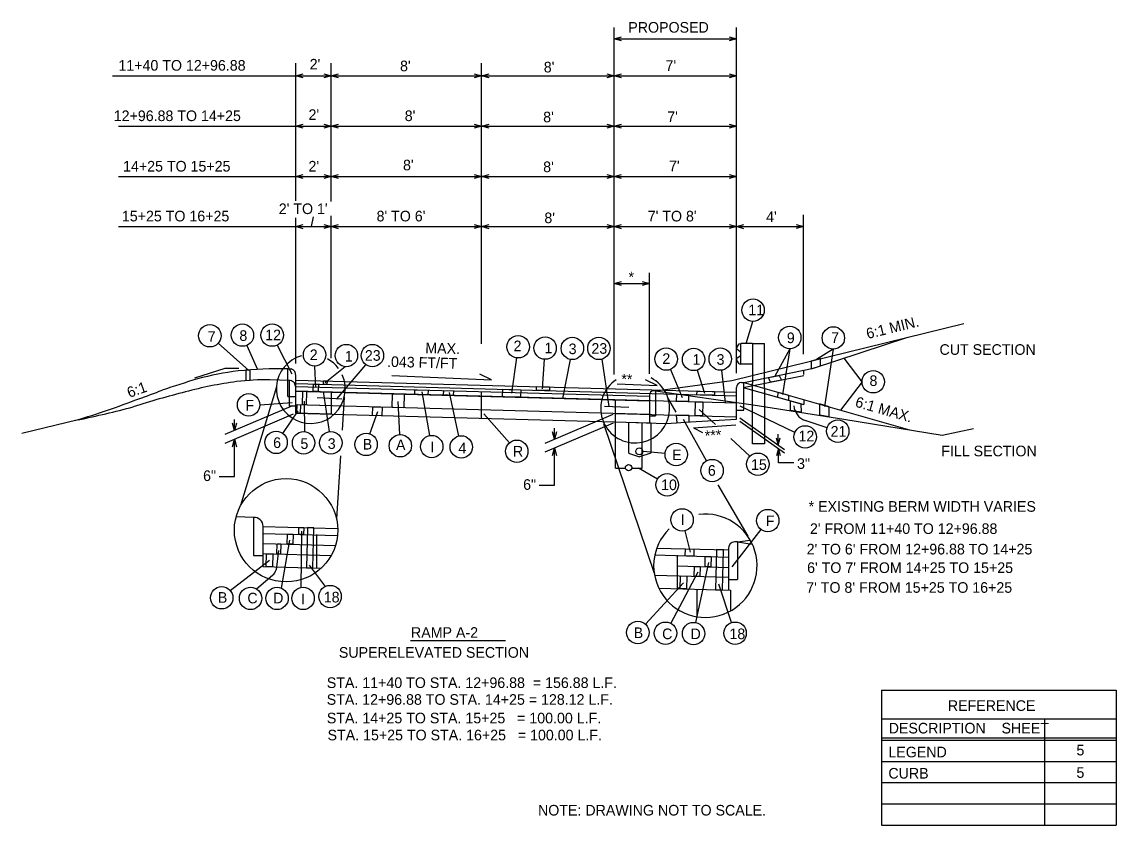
# Model space of a CAD drawing. Extents: x -210 to 558, y -150 to 205.
# Drawn here: x 374.7 to 436.5, y -53.8 to -8.4 of the extents above; entities that cross this region are included whole.
import ezdxf

# ---------------------------------------------------------------- set-up
doc = ezdxf.new("R2010")
doc.units = 0
for name, color, linetype in [('Level 4', 7, 'Continuous'), ('Level 6', 7, 'Continuous'), ('Level 60', 7, 'Continuous'), ('Level 7', 7, 'Continuous')]:
    doc.layers.add(name, color=color, linetype=linetype)

msp = doc.modelspace()

# ---------------------------------------------------------------- linework, layer by layer
at = {"layer": 'Level 4'}
for p, q in [((408.184, -28.302), (408.184, -8.684)), ((415.094, -28.229), (415.094, -8.684)), ((408.184, -9.336), (415.094, -9.336)), ((390.196, -18.485), (390.196, -10.711)), ((392.196, -18.522), (392.196, -10.711)), ((400.696, -26.569), (400.696, -10.711)), ((379.849, -11.429), (390.196, -11.429)), ((390.196, -11.429), (392.196, -11.429)), ((392.196, -11.429), (400.696, -11.429)), ((400.549, -11.411), (400.966, -11.411)), ((400.696, -11.429), (408.184, -11.429)), ((408.184, -11.429), (415.094, -11.429)), ((380.181, -14.268), (390.196, -14.268)), ((390.196, -14.268), (392.196, -14.268)), ((392.196, -14.268), (400.696, -14.268)), ((400.549, -14.25), (400.966, -14.25)), ((400.696, -14.268), (408.184, -14.268)), ((408.184, -14.268), (415.094, -14.268)), ((380.181, -17.107), (390.196, -17.107)), ((390.196, -17.107), (392.196, -17.107)), ((392.196, -17.107), (400.696, -17.107)), ((400.549, -17.089), (400.966, -17.089)), ((400.696, -17.107), (408.184, -17.107)), ((408.184, -17.107), (415.094, -17.107)), ((390.196, -27.673), (390.196, -19.448)), ((391.184, -19.392), (391.071, -19.94)), ((392.196, -27.378), (392.196, -19.335)), ((418.884, -27.152), (418.884, -19.284)), ((380.181, -19.946), (390.196, -19.946)), ((390.196, -19.946), (392.196, -19.946)), ((392.196, -19.946), (400.696, -19.946)), ((400.549, -19.928), (400.966, -19.928)), ((400.696, -19.946), (408.184, -19.946)), ((408.184, -19.946), (418.884, -19.946)), ((410.184, -28.255), (410.184, -22.558)), ((408.184, -23.158), (410.184, -23.158)), ((415.652, -26.553), (416.028, -25.298)), ((385.816, -26.532), (387.54, -28.071)), ((387.439, -26.655), (388.041, -28.017)), ((389.157, -26.64), (389.983, -28.255)), ((418.105, -26.847), (417.238, -28.44)), ((418.105, -26.847), (417.7, -29.422)), ((420.566, -26.871), (419.619, -27.457)), ((420.566, -26.871), (420.061, -30.103)), ((392.538, -29.66), (394.166, -27.754)), ((402.671, -27.362), (402.384, -29.353)), ((404.239, -27.439), (404.121, -29.12)), ((405.701, -27.446), (405.267, -29.657)), ((407.495, -27.434), (407.88, -30.103)), ((422.189, -28.711), (421.179, -27.379)), ((386.196, -27.962), (384.483, -28.51)), ((386.979, -27.965), (386.196, -27.962)), ((391.258, -27.849), (391.318, -29.014)), ((392.99, -27.863), (391.862, -28.772)), ((395.631, -28.356), (401.257, -28.609)), ((401.257, -28.609), (400.592, -28.289)), ((411.369, -28.011), (412.034, -29.609)), ((412.869, -28.053), (413.284, -29.354)), ((414.254, -28.056), (414.465, -29.875)), ((408.363, -28.838), (410.621, -28.922)), ((410.621, -28.922), (409.956, -28.602)), ((422.189, -28.711), (420.973, -30.313)), ((392.112, -31.525), (391.759, -29.264)), ((397.771, -31.753), (397.347, -29.285)), ((399.417, -31.778), (398.887, -29.321)), ((390.019, -30.068), (386.183, -31.7)), ((388.171, -30.016), (389.992, -29.878)), ((390.703, -31.529), (390.697, -29.808)), ((396.075, -31.69), (395.986, -29.822)), ((412.989, -30.274), (413.904, -31.119)), ((418.387, -31.584), (415.31, -30.095)), ((390.051, -30.552), (386.183, -32.197)), ((386.738, -31.464), (386.738, -30.835)), ((389.467, -31.626), (390.335, -30.351)), ((394.386, -31.655), (394.84, -30.395)), ((402.265, -32.166), (400.821, -30.525)), ((408.102, -30.565), (404.266, -32.197)), ((413.409, -33.176), (412.11, -30.837)), ((415.285, -30.758), (417.806, -32.545)), ((420.216, -31.306), (418.975, -30.906)), ((408.133, -31.049), (404.266, -32.694)), ((404.82, -31.961), (404.82, -31.332)), ((412.671, -31.315), (415.064, -31.144)), ((412.671, -31.315), (413.185, -31.579)), ((415.285, -30.941), (417.815, -32.733)), ((386.738, -34.061), (386.738, -31.961)), ((414.77, -31.919), (415.845, -32.912)), ((417.451, -32.295), (417.451, -31.666)), ((404.82, -34.558), (404.82, -32.459)), ((411.072, -32.763), (409.817, -32.643)), ((417.461, -33.295), (417.461, -32.48)), ((418.337, -33.295), (417.461, -33.295)), ((410.634, -34.216), (409.553, -33.59)), ((385.862, -34.061), (386.738, -34.061)), ((403.944, -34.558), (404.82, -34.558)), ((416.474, -37.06), (414.84, -39.173)), ((389.395, -40.371), (389.868, -37.672)), ((390.516, -37.148), (390.486, -40.33)), ((412.177, -37.132), (412.481, -38.339)), ((389.228, -38.24), (389.086, -39.332)), ((386.493, -40.501), (388.722, -38.8)), ((412.806, -42.324), (413.539, -38.929)), ((390.96, -39.084), (391.86, -40.281)), ((411.384, -42.363), (412.929, -39.458)), ((387.987, -40.416), (388.891, -39.643)), ((409.948, -42.415), (412.095, -40.068)), ((414.819, -42.32), (414.108, -40.149)), ((396.676, -43.325), (402.05, -43.325)), ((423.287, -46.13), (423.287, -53.765)), ((423.287, -46.13), (436.542, -46.13)), ((436.542, -46.13), (436.542, -53.765)), ((423.287, -47.765), (436.542, -47.765)), ((432.497, -47.765), (432.497, -53.765)), ((423.287, -48.839), (436.542, -48.839)), ((423.287, -48.965), (436.542, -48.965)), ((423.287, -50.165), (436.542, -50.165)), ((423.287, -51.365), (436.542, -51.365)), ((423.287, -52.565), (436.542, -52.565)), ((423.287, -53.765), (436.542, -53.765))]:
    msp.add_line(p, q, dxfattribs=at)
for points in [[(408.604, -9.452), (408.184, -9.336), (408.604, -9.224)], [(414.674, -9.22), (415.094, -9.336), (414.674, -9.448)], [(390.616, -11.545), (390.196, -11.429), (390.616, -11.317)], [(391.776, -11.313), (392.196, -11.429), (391.776, -11.541)], [(392.616, -11.545), (392.196, -11.429), (392.616, -11.317)], [(400.276, -11.313), (400.696, -11.429), (400.276, -11.541)], [(401.116, -11.545), (400.696, -11.429), (401.116, -11.317)], [(407.764, -11.313), (408.184, -11.429), (407.764, -11.541)], [(408.604, -11.545), (408.184, -11.429), (408.604, -11.317)], [(414.674, -11.313), (415.094, -11.429), (414.674, -11.541)], [(390.616, -14.384), (390.196, -14.268), (390.616, -14.156)], [(391.776, -14.152), (392.196, -14.268), (391.776, -14.38)], [(392.616, -14.384), (392.196, -14.268), (392.616, -14.156)], [(400.276, -14.152), (400.696, -14.268), (400.276, -14.38)], [(401.116, -14.384), (400.696, -14.268), (401.116, -14.156)], [(407.764, -14.152), (408.184, -14.268), (407.764, -14.38)], [(408.604, -14.384), (408.184, -14.268), (408.604, -14.156)], [(414.674, -14.152), (415.094, -14.268), (414.674, -14.38)], [(390.616, -17.223), (390.196, -17.107), (390.616, -16.995)], [(391.776, -16.991), (392.196, -17.107), (391.776, -17.219)], [(392.616, -17.223), (392.196, -17.107), (392.616, -16.995)], [(400.276, -16.991), (400.696, -17.107), (400.276, -17.219)], [(401.116, -17.223), (400.696, -17.107), (401.116, -16.995)], [(407.764, -16.991), (408.184, -17.107), (407.764, -17.219)], [(408.604, -17.223), (408.184, -17.107), (408.604, -16.995)], [(414.674, -16.991), (415.094, -17.107), (414.674, -17.219)], [(390.616, -20.062), (390.196, -19.946), (390.616, -19.834)], [(391.776, -19.83), (392.196, -19.946), (391.776, -20.058)], [(392.616, -20.062), (392.196, -19.946), (392.616, -19.834)], [(400.276, -19.83), (400.696, -19.946), (400.276, -20.058)], [(401.116, -20.062), (400.696, -19.946), (401.116, -19.834)], [(407.764, -19.83), (408.184, -19.946), (407.764, -20.058)], [(408.604, -20.062), (408.184, -19.946), (408.604, -19.834)], [(414.674, -19.83), (415.094, -19.946), (414.674, -20.058)], [(415.514, -20.062), (415.094, -19.946), (415.514, -19.834)], [(418.464, -19.83), (418.884, -19.946), (418.464, -20.058)], [(408.604, -23.274), (408.184, -23.158), (408.604, -23.046)], [(409.764, -23.042), (410.184, -23.158), (409.764, -23.27)], [(386.854, -31.044), (386.738, -31.464), (386.626, -31.044)], [(386.622, -32.381), (386.738, -31.961), (386.85, -32.381)], [(404.936, -31.541), (404.82, -31.961), (404.708, -31.541)], [(417.335, -31.875), (417.451, -32.295), (417.563, -31.875)], [(404.704, -32.879), (404.82, -32.459), (404.932, -32.879)], [(417.577, -32.9), (417.461, -32.48), (417.349, -32.9)]]:
    msp.add_lwpolyline(points, dxfattribs=at)
for points in [[(419.308, -27.539), (419.322, -27.979), (419.849, -27.815), (419.846, -27.389)], [(416.896, -28.471), (417.509, -28.351), (417.638, -28.612), (417.026, -28.732)], [(417.443, -29.306), (418.043, -29.476), (418.041, -29.767), (417.44, -29.597)], [(418.144, -29.793), (418.737, -29.959), (418.747, -30.437), (418.152, -30.344)], [(419.79, -29.96), (419.789, -30.583), (420.328, -30.674), (420.324, -30.123)]]:
    msp.add_lwpolyline(points, close=True, dxfattribs=at)
for centre in [(416.03, -24.664), (385.343, -26.11), (387.183, -26.075), (388.868, -26.075), (418.106, -26.213), (420.567, -26.237), (391.263, -27.189), (402.761, -26.734), (404.283, -26.806), (405.823, -26.824), (407.323, -26.824), (393.057, -27.233), (394.527, -27.233), (411.125, -27.426), (412.676, -27.449), (414.181, -27.426), (422.823, -28.712), (387.537, -30.015), (420.818, -31.506), (389.088, -32.135), (418.975, -31.83), (390.642, -32.161), (392.178, -32.161), (394.172, -32.252), (396.106, -32.324), (397.878, -32.377), (399.551, -32.397), (402.684, -32.642), (411.692, -32.823), (416.302, -33.372), (413.717, -33.73), (411.183, -34.533), (412.022, -36.517), (416.862, -36.558), (386.013, -40.916), (387.647, -40.951), (389.139, -40.951), (390.613, -40.951), (392.138, -40.851), (409.52, -42.882), (411.086, -42.923), (412.672, -42.943), (415.016, -42.923)]:
    msp.add_circle(centre, 0.634, dxfattribs=at)
for centre, radius, start, end in [((419.305, -29.997), 0.967, 184.63452, 250.04639), ((388.603, -39.245), 0.491, 305.90709, 349.76504)]:
    msp.add_arc(centre, radius, start, end, dxfattribs=at)
at = {"layer": 'Level 6'}
for p, q in [((414.826, -28.635), (427.937, -25.416)), ((389.82, -28.64), (388.731, -28.607)), ((389.82, -28.64), (389.82, -30.072)), ((390.175, -28.959), (390.175, -30.487)), ((390.175, -28.974), (410.184, -29.524)), ((410.517, -29.221), (414.826, -28.635)), ((390.175, -29.239), (410.184, -29.789)), ((400.696, -30.776), (400.696, -29.264)), ((410.184, -29.47), (410.184, -31.037)), ((410.517, -29.221), (410.416, -29.221)), ((410.517, -29.221), (410.517, -30.631)), ((410.517, -29.221), (416.037, -30.01)), ((389.82, -30.072), (390.175, -30.072)), ((390.175, -30.001), (410.184, -30.551)), ((416.037, -30.01), (421.152, -30.817)), ((377.912, -30.866), (374.726, -31.638)), ((390.175, -30.487), (410.263, -31.039)), ((410.184, -30.631), (410.517, -30.631)), ((421.152, -30.817), (426.711, -31.73)), ((408.989, -31.004), (408.989, -32.734)), ((410.263, -31.039), (410.263, -32.734)), ((426.711, -31.73), (428.492, -31.361)), ((408.989, -32.739), (409.626, -32.948)), ((410.263, -32.739), (409.626, -32.948)), ((387.811, -36.381), (386.827, -36.352)), ((387.811, -36.381), (387.811, -38.53)), ((388.344, -36.86), (388.344, -39.152)), ((388.344, -36.883), (392.57, -36.999)), ((388.344, -37.28), (392.557, -37.395)), ((391.375, -37.334), (391.375, -39.235)), ((415.148, -37.762), (415.878, -37.663)), ((388.379, -37.846), (392.443, -37.957)), ((410.599, -38.106), (414.648, -38.217)), ((414.648, -38.136), (414.648, -40.486)), ((415.148, -37.762), (414.996, -37.762)), ((415.148, -37.762), (415.148, -39.877)), ((415.148, -37.762), (415.977, -37.881)), ((387.811, -38.53), (388.344, -38.53)), ((388.344, -38.423), (392.199, -38.529)), ((410.456, -38.499), (414.648, -38.614)), ((411.759, -40.407), (411.759, -38.505)), ((388.344, -39.152), (391.638, -39.242)), ((411.759, -39.12), (414.648, -39.2)), ((410.464, -39.642), (414.648, -39.757)), ((414.648, -39.877), (415.148, -39.877)), ((410.713, -40.378), (414.767, -40.489)), ((412.856, -40.437), (412.856, -41.992)), ((414.767, -40.489), (414.767, -41.657))]:
    msp.add_line(p, q, dxfattribs=at)
msp.add_circle((409.61, -32.648), 0.196, dxfattribs=at)
for centre, radius, start, end in [((389.771, -50.813), 22.298, 97.5041, 105.09419), ((388.416, -40.406), 11.803, 88.4676, 97.57992), ((389.842, -28.981), 0.342, 1.12623, 93.69626), ((396.565, -78.792), 51.086, 104.27965, 107.71771), ((410.425, -29.463), 0.242, 92.27579, 181.84757), ((364.744, 31.6), 63.839, 281.90418, 284.7694), ((387.844, -36.893), 0.513, 1.12623, 93.69626), ((415.011, -38.125), 0.363, 92.27579, 181.84757)]:
    msp.add_arc(centre, radius, start, end, dxfattribs=at)
at = {"layer": 'Level 60'}
for points in [[(387.62, -28.051), (387.385, -28.065), (387.385, -28.64), (387.627, -28.626)], [(391.18, -29.247), (391.191, -28.845), (391.479, -28.853), (391.468, -29.255)], [(391.764, -28.861), (391.77, -28.655), (391.967, -28.66), (391.961, -28.866)], [(403.799, -29.191), (403.804, -28.986), (404.535, -29.006), (404.529, -29.212)], [(390.573, -30.012), (390.594, -29.25), (390.806, -29.256), (390.785, -30.018)], [(395.646, -30.16), (395.667, -29.398), (396.328, -29.417), (396.307, -30.178)], [(396.918, -29.433), (396.925, -29.169), (397.671, -29.189), (397.664, -29.453)], [(398.548, -29.458), (398.565, -29.196), (399.102, -29.229), (399.086, -29.491)], [(401.881, -29.56), (401.893, -29.139), (402.904, -29.167), (402.892, -29.588)], [(411.716, -29.811), (411.727, -29.409), (412.387, -29.428), (412.376, -29.829)], [(412.862, -29.441), (412.867, -29.235), (413.858, -29.262), (413.853, -29.468)], [(390.266, -30.489), (390.279, -30.004), (390.461, -30.009), (390.447, -30.494)], [(394.535, -30.615), (394.549, -30.13), (395.075, -30.144), (395.062, -30.63)], [(412.768, -30.622), (412.79, -29.841), (413.198, -29.852), (413.177, -30.633)], [(411.717, -31.023), (412.422, -30.973), (412.422, -30.613), (411.692, -30.592)], [(390.369, -37.335), (390.38, -36.939), (390.654, -36.947), (390.643, -37.343)], [(390.867, -36.952), (390.805, -39.219), (391.16, -39.229), (391.222, -36.962)], [(389.713, -37.882), (389.728, -37.318), (390.051, -37.326), (390.035, -37.891)], [(389.126, -38.444), (389.142, -37.867), (389.348, -37.872), (389.332, -38.45)], [(412.205, -38.547), (412.216, -38.151), (412.695, -38.164), (412.684, -38.56)], [(413.973, -38.199), (413.911, -40.466), (414.304, -40.477), (414.367, -38.21)], [(388.53, -39.157), (388.55, -38.428), (388.897, -38.438), (388.876, -39.166)], [(413.318, -39.163), (413.335, -38.578), (413.67, -38.587), (413.654, -39.173)], [(412.712, -39.704), (412.727, -39.147), (413.047, -39.156), (413.031, -39.713)], [(411.912, -40.411), (411.932, -39.683), (412.292, -39.693), (412.272, -40.421)]]:
    msp.add_lwpolyline(points, close=True, dxfattribs=at)
at = {"layer": 'Level 7'}
for p, q in [((415.107, -26.768), (415.255, -26.563)), ((415.255, -26.563), (415.342, -26.548)), ((416.009, -26.548), (415.342, -26.548)), ((415.342, -27.715), (415.342, -26.548)), ((416.009, -26.548), (416.009, -28.798)), ((416.009, -26.548), (416.675, -26.548)), ((416.675, -29.051), (416.675, -26.548)), ((419.449, -27.95), (424.771, -26.193)), ((415.312, -27.023), (415.122, -26.875)), ((415.255, -27.699), (415.107, -27.495)), ((415.122, -27.387), (415.312, -27.24)), ((415.255, -27.699), (415.342, -27.715)), ((416.009, -27.715), (415.342, -27.715)), ((389.747, -29.547), (389.747, -27.979)), ((389.747, -27.979), (389.931, -27.979)), ((390.196, -30.487), (390.196, -28.379)), ((415.482, -29.041), (418.892, -28.349)), ((415.506, -28.751), (419.449, -27.95)), ((418.884, -28.065), (418.884, -28.31)), ((389.103, -28.999), (387.084, -35.709)), ((390.196, -28.612), (408.257, -29.108)), ((390.196, -28.818), (408.257, -29.314)), ((415.095, -30.833), (415.095, -29.043)), ((415.377, -28.751), (415.506, -28.751)), ((415.482, -29.041), (418.892, -30.002)), ((415.506, -30.31), (415.506, -28.751)), ((415.506, -28.751), (424.874, -31.428)), ((416.009, -32.215), (416.009, -28.798)), ((416.675, -29.051), (416.675, -32.215)), ((389.747, -29.547), (390.196, -29.547)), ((390.196, -29.22), (408.216, -29.715)), ((391.416, -29.607), (392.793, -29.671)), ((392.196, -29.275), (392.196, -30.542)), ((392.938, -29.583), (392.819, -31.443)), ((408.257, -29.108), (415.095, -29.296)), ((408.257, -29.314), (415.095, -29.502)), ((411.179, -29.579), (411.675, -30.435)), ((390.196, -30.001), (392.196, -30.056)), ((407.64, -30.092), (409.016, -30.156)), ((408.216, -29.715), (415.095, -29.904)), ((408.257, -30.984), (408.257, -29.716)), ((418.892, -29.71), (418.892, -30.002)), ((392.196, -30.542), (390.196, -30.487)), ((408.257, -30.498), (415.095, -30.686)), ((412.494, -30.968), (415.095, -30.833)), ((415.095, -30.31), (415.506, -30.31)), ((407.587, -31.068), (410.445, -39.52)), ((408.257, -30.984), (411.149, -31.063)), ((408.257, -33.59), (408.257, -30.984)), ((409.767, -33.59), (409.767, -31.027)), ((411.149, -31.063), (412.494, -30.968)), ((416.675, -32.215), (416.009, -32.215)), ((392.726, -32.895), (392.498, -36.452)), ((408.257, -33.59), (408.822, -33.59)), ((409.181, -33.59), (409.767, -33.59)), ((414.046, -34.528), (415.734, -37.444))]:
    msp.add_line(p, q, dxfattribs=at)
for centre, radius in [((409.001, -33.563), 0.18), ((389.651, -37.102), 2.92)]:
    msp.add_circle(centre, radius, dxfattribs=at)
for centre, radius, start, end in [((415.17, -26.813), 0.0781, 144.08393, 232.1285), ((415.264, -27.178), 0.0781, 307.8715, 360), ((391.047, -29.12), 1.947, 105.71295, 23.99916), ((391.047, -29.12), 1.947, 36.81944, 61.15971), ((415.17, -27.449), 0.0781, 127.8715, 215.91607), ((389.118, -45.289), 17.325, 97.20085, 104.96984), ((389.478, -54.027), 26.049, 89.40827, 95.57705), ((389.838, -28.328), 0.361, 351.83326, 75.13882), ((401.704, -85.325), 59.281, 106.72669, 108.74418), ((409.371, -30.222), 1.947, 123.2425, 62.52215), ((415.382, -29.038), 0.287, 91.07893, 181.04781), ((372.456, -3.557), 27.585, 288.76299, 291.69708), ((364.644, 13.5), 46.288, 286.48159, 291.12853), ((413.337, -39.111), 2.92, 134.46673, 97.29987)]:
    msp.add_arc(centre, radius, start, end, dxfattribs=at)

# ---------------------------------------------------------------- texts
at = {"layer": 'Level 4'}
for s, p in [('PROPOSED', (408.983, -8.984)), ("2'", (390.985, -11.066)), ('11+40 TO 12+96.88', (380.181, -11.132)), ("8'", (396.09, -11.165)), ("8'", (404.21, -11.232)), ("7'", (411.087, -11.149)), ('12+96.88 TO 14+25', (379.916, -13.982)), ("2'", (390.919, -13.916)), ("8'", (396.355, -13.982)), ("8'", (404.176, -14.049)), ("7'", (411.186, -14.032)), ('14+25 TO 15+25', (380.443, -16.833)), ("2'", (390.919, -16.833)), ("8'", (396.258, -16.766)), ("8'", (404.176, -16.866)), ("7'", (411.286, -16.816)), ('15+25 TO 16+25', (380.377, -19.65)), ("2' TO 1'", (389.239, -19.236)), ("8' TO 6'", (394.764, -19.65)), ("8'", (404.243, -19.749)), ("7' TO 8'", (410.083, -19.652)), ("4'", (416.772, -19.689)), ('*', (408.997, -23.091)), ('11', (415.765, -24.953)), ('7', (385.225, -26.454)), ('8', (387.014, -26.402)), ('12', (388.472, -26.367)), ('9', (417.94, -26.529)), ('7', (420.445, -26.514)), ('2', (402.503, -26.986)), ('1', (404.255, -27.103)), ('3', (405.615, -27.151)), ('23', (406.901, -27.13)), ('2', (390.989, -27.487)), ('1', (392.973, -27.569)), ('23', (394.101, -27.525)), ('2', (410.907, -27.704)), ('1', (412.613, -27.752)), ('3', (413.972, -27.753)), ('CUT SECTION', (426.565, -27.19)), ('**', (408.593, -28.866)), ('8', (422.611, -28.952)), ('F', (387.351, -30.339)), ('12', (418.599, -32.079)), ('21', (420.413, -31.814)), ('6', (388.92, -32.451)), ('5', (390.462, -32.506)), ('3', (392.005, -32.505)), ('B', (393.98, -32.54)), ('A', (395.861, -32.576)), ('I', (397.795, -32.701)), ('4', (399.388, -32.755)), ('R', (402.469, -32.942)), ('E', (411.466, -33.141)), ('FILL SECTION', (426.664, -32.924)), ('15', (415.917, -33.691)), ('3"', (418.518, -33.634)), ('6"', (384.963, -34.321)), ('6', (413.479, -34.023)), ('6"', (403.045, -34.819)), ('10', (410.836, -34.834)), ('* EXISTING BERM WIDTH VARIES', (419.171, -36.057)), ('I', (411.953, -36.809)), ('F', (416.752, -36.87)), ("2' FROM 11+40 TO 12+96.88", (419.246, -37.311)), ("2' TO 6' FROM 12+96.88 TO 14+25", (419.061, -38.47)), ("6' TO 7' FROM 14+25 TO 15+25", (419.086, -39.517)), ("7' TO 8' FROM 15+25 TO 16+25", (419.037, -40.637)), ('B', (385.796, -41.2)), ('C', (387.466, -41.235)), ('D', (388.922, -41.235)), ('I', (390.503, -41.288)), ('18', (391.781, -41.182)), ('RAMP A-2', (396.708, -43.18)), ('B', (409.289, -43.195)), ('C', (410.895, -43.256)), ('18', (414.698, -43.256)), ('D', (412.502, -43.256)), ('SUPERELEVATED SECTION', (392.634, -44.307)), ('STA. 11+40 TO STA. 12+96.88  = 156.88 L.F.', (391.952, -46.017)), ('STA. 12+96.88 TO STA. 14+25 = 128.12 L.F.', (391.947, -46.965)), ('REFERENCE', (427.037, -47.311)), ('STA. 14+25 TO STA. 15+25   = 100.00 L.F.', (391.954, -48.014)), ('DESCRIPTION    SHEET', (423.694, -48.585)), ('STA. 15+25 TO STA. 16+25   = 100.00 L.F.', (391.995, -48.975)), ('LEGEND', (423.678, -49.935)), ('5', (434.302, -49.826)), ('CURB', (423.678, -51.135)), ('5', (434.302, -51.095)), ('NOTE: DRAWING NOT TO SCALE.', (403.884, -53.223))]:
    msp.add_text(s, height=0.6, dxfattribs=at).set_placement(p)
for s, rotation, p in [('6:1 MIN.', 13.79506, (422.508, -26.298)), ('MAX.', 358.42591, (397.51, -27.094)), ('.043 FT/FT', 358.42591, (395.348, -27.866)), ('6:1', 19.53014, (380.795, -29.627)), ('6:1 MAX.', 344.04801, (421.759, -30.109)), ('***', 4.07739, (413.33, -32.066))]:
    msp.add_text(s, height=0.6, rotation=rotation, dxfattribs=at).set_placement(p)

doc.saveas('drawing.dxf')
